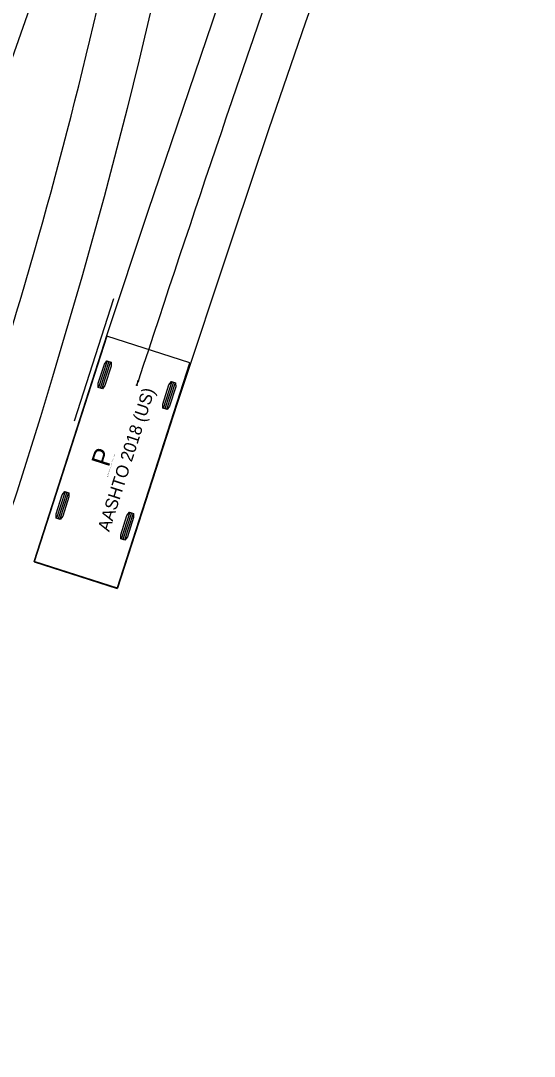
# Model space of a CAD drawing. Extents: x 2175591 to 2194071, y 76570 to 86955.
# Drawn here: x 2192945.4 to 2192986.5, y 86502.5 to 86585.5 of the extents above; entities that cross this region are included whole.
import ezdxf

# ---------------------------------------------------------------- set-up
doc = ezdxf.new("R2010")
doc.units = 0
doc.layers.add('C-UTIL-STRM-TEXT', color=7, linetype='Continuous')

msp = doc.modelspace()

# ---------------------------------------------------------------- linework, layer by layer
at = {"layer": 'C-UTIL-STRM-TEXT'}
for p, q in [((2192949.7, 86553.437), (2192952.858, 86563.238)), ((2192952.285, 86560.231), (2192946.459, 86542.147)), ((2192958.948, 86558.085), (2192952.285, 86560.231)), ((2192952.285, 86560.231), (2192952.285, 86560.231)), ((2192952.32, 86558.25), (2192951.63, 86556.109)), ((2192952.454, 86558.207), (2192951.764, 86556.065)), ((2192952.588, 86558.164), (2192951.898, 86556.022)), ((2192953.122, 86540), (2192958.948, 86558.085)), ((2192957.496, 86556.583), (2192956.806, 86554.441)), ((2192957.63, 86556.54), (2192956.94, 86554.398)), ((2192957.764, 86556.497), (2192957.074, 86554.355)), ((2192948.947, 86547.78), (2192948.257, 86545.639)), ((2192949.081, 86547.737), (2192948.391, 86545.595)), ((2192949.215, 86547.694), (2192948.525, 86545.552)), ((2192954.123, 86546.113), (2192953.433, 86543.971)), ((2192954.257, 86546.07), (2192953.567, 86543.928)), ((2192954.39, 86546.026), (2192953.7, 86543.885)), ((2192946.459, 86542.147), (2192953.122, 86540))]:
    msp.add_line(p, q, dxfattribs=at)
for points in [[(2192946.466, 86542.169), (2192952.348, 86560.426), (2192955.607, 86570.241), (2192960.75, 86585.404), (2192961.895, 86588.897), (2192963.163, 86592.39), (2192966.018, 86600.556), (2192966.644, 86602.175), (2192967.364, 86603.747), (2192968.662, 86606.186), (2192970.203, 86608.885), (2192971.822, 86611.538), (2192973.71, 86614.428), (2192975.691, 86617.256), (2192977.763, 86620.019), (2192979.923, 86622.712), (2192982.17, 86625.335), (2192984.5, 86627.883), (2192986.912, 86630.354)], [(2192987.069, 86618.864), (2192985.431, 86616.901), (2192983.649, 86614.643), (2192981.934, 86612.334), (2192980.287, 86609.976), (2192978.881, 86607.84), (2192977.366, 86605.395), (2192975.923, 86602.907), (2192974.552, 86600.377), (2192973.397, 86598.098), (2192972.175, 86595.514), (2192971.032, 86592.908), (2192969.956, 86590.245), (2192969.157, 86588.115), (2192968.172, 86585.314), (2192965.266, 86576.823), (2192962.396, 86568.318), (2192957.9, 86554.748), (2192953.129, 86540.023), (2192946.466, 86542.169)], [(2192912.156, 86501.045), (2192914.736, 86506.091), (2192917.378, 86511.477), (2192919.37, 86515.698), (2192921.17, 86519.639), (2192923.056, 86523.908), (2192924.887, 86528.2), (2192926.539, 86532.207), (2192928.264, 86536.542), (2192929.936, 86540.899), (2192931.557, 86545.275), (2192934.812, 86554.377), (2192949.166, 86595.214)], [(2192955.877, 86586.569), (2192954.877, 86582.353), (2192953.921, 86578.47), (2192952.068, 86571.375), (2192950.271, 86564.955), (2192947.94, 86556.957), (2192946.984, 86553.764), (2192945.072, 86547.726), (2192944.016, 86544.565), (2192942.927, 86541.414), (2192940.763, 86535.466), (2192938.478, 86529.559), (2192937.226, 86526.47), (2192935.941, 86523.394), (2192933.408, 86517.589), (2192930.758, 86511.841), (2192927.989, 86506.145), (2192925.104, 86500.507)], [(2192954.697, 86556.303), (2192954.799, 86556.62)]]:
    msp.add_lwpolyline(points, dxfattribs=at)
for points in [[(2192952.287, 86558.261), (2192952.621, 86558.153), (2192952.625, 86557.821), (2192952.128, 86556.279), (2192951.931, 86556.012), (2192951.597, 86556.119), (2192951.593, 86556.452), (2192952.09, 86557.993)], [(2192957.463, 86556.593), (2192957.797, 86556.486), (2192957.801, 86556.154), (2192957.304, 86554.612), (2192957.107, 86554.344), (2192956.773, 86554.452), (2192956.769, 86554.784), (2192957.265, 86556.326)], [(2192948.914, 86547.791), (2192949.248, 86547.683), (2192949.252, 86547.351), (2192948.755, 86545.809), (2192948.558, 86545.542), (2192948.224, 86545.649), (2192948.22, 86545.981), (2192948.717, 86547.523)], [(2192954.089, 86546.123), (2192954.424, 86546.016), (2192954.428, 86545.684), (2192953.931, 86544.142), (2192953.734, 86543.874), (2192953.399, 86543.982), (2192953.395, 86544.314), (2192953.892, 86545.856)]]:
    msp.add_lwpolyline(points, close=True, dxfattribs=at)
for centre in [(2192954.799, 86556.62), (2192954.799, 86556.62), (2192954.697, 86556.303)]:
    msp.add_circle(centre, 0.0417, dxfattribs=at)
for centre, radius, start, end in [((2192560.662, 86677.393), 401.302, 342.77388, 348.50463), ((2194950.606, 85902.069), 2100.401, 160.697775, 161.842429)]:
    msp.add_arc(centre, radius, start, end, dxfattribs=at)

# ---------------------------------------------------------------- texts
for s, height, p in [('AASHTO 2018 (US)', 1, (2192952.477, 86544.504)), ('P', 1.5, (2192952.436, 86549.677)), ('(c) 2024 Transoft Solutions, Inc. All rights reserved.', 0.06, (2192952.355, 86548.937))]:
    msp.add_text(s, height=height, rotation=72.14249, dxfattribs=at).set_placement(p)

doc.saveas('drawing.dxf')
